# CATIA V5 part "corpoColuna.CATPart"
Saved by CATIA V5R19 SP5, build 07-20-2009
Part number: CorpoColuna
Bounding box of the stored display mesh (mm): x -17 to 2, y -64.929 to 64.929, z -64.807 to 40
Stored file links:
  Z:\UA\ATLAS\atlascar\ServoPiloto\dir\suportePotenciometro\V2\corpoColuna.CATPart
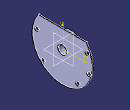
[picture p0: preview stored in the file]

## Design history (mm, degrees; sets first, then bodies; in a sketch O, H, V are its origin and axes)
Body1 (main body)
  Sketch1 on yz-plane, origin (0, 0, 0), H (0, 1, 0), V (0, 0, 1)
    circle A1 centre (0, 0) radius 9.5
    point P1 (32.249, -47)
    circle A2 centre (32.249, -47) radius 4
    point P2 (35.8761, -48.6865)
    point P3 (53.376, 20)
    circle A3 centre (53.376, 20) radius 4
    point P4 (-55.9285, 11)
    circle A4 centre (-55.9285, 11) radius 4
    point P5 (15.2785, -51)
    point P6 (14.3871, -51.0132)
    construction circle A5 centre (0, 0) radius 57
    construction circle A6 centre (0, 0) radius 59.5
    circle A7 centre (56.8926, -17.4206) radius 4
    point P7 (56.8926, -17.4206)
    circle A8 centre (-42.7635, -41.3706) radius 4
    point P8 (-42.7635, -41.3706)
    arc A9 centre (0, 0) radius 65 from (-51.2348, 40) to (51.2348, 40) ccw
    line L1 (51.2348, 40) -> (-51.2348, 40)
    radius A1 = 9.5
    radius A2 = 4 {= Sketch1.radius(A4)}
    distance H P3 = 20
    radius A3 = 4 {= Sketch1.radius(A4)}
    distance H P4 = 11
    radius A4 = 4
    radius A5 = 57
    radius A6 = 59.5
    radius A8 = 4 {= Sketch1.radius(A4)}
    radius A7 = 4 {= Sketch1.radius(A4)}
    distance P4 P8 = 54
    distance P1 P7 = 38.5
    radius A9 = 65
    distance L1 H = 40
    coincidence: A2 P2, A5 P3, P4 A5, P1 A5, P7 A6, P8 A6
    horizontal: L1 H
  Pad1: profile Sketch1, direction (1, 0, 0), length 2
  Sketch2 on start face of Pad1, origin (0, 0, 0), H (0, -1, 0), V (0, 0, 1)
    projected circle E1 centre (0, 0) radius 9.5 from Sketch1.A1
    circle A1 centre (0, 0) radius 27.5
    radius A1 = 27.5
  Pad2: profile Sketch2, direction (-1, 0, 0), length 17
